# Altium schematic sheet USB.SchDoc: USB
size A4; Date: Not used; ApprovedBy: Not used; CheckedBy: Not used; Author: Not used; CompanyName: STMicroelectronics; DrawnBy: Not used; Engineer: Not used; Organization: Not used; Address1: Not used; Address2: Not used; Address3: Not used; Address4: Not used; DocumentNumber: 7; Revision: Not used; SheetNumber: 7; SheetTotal: 8
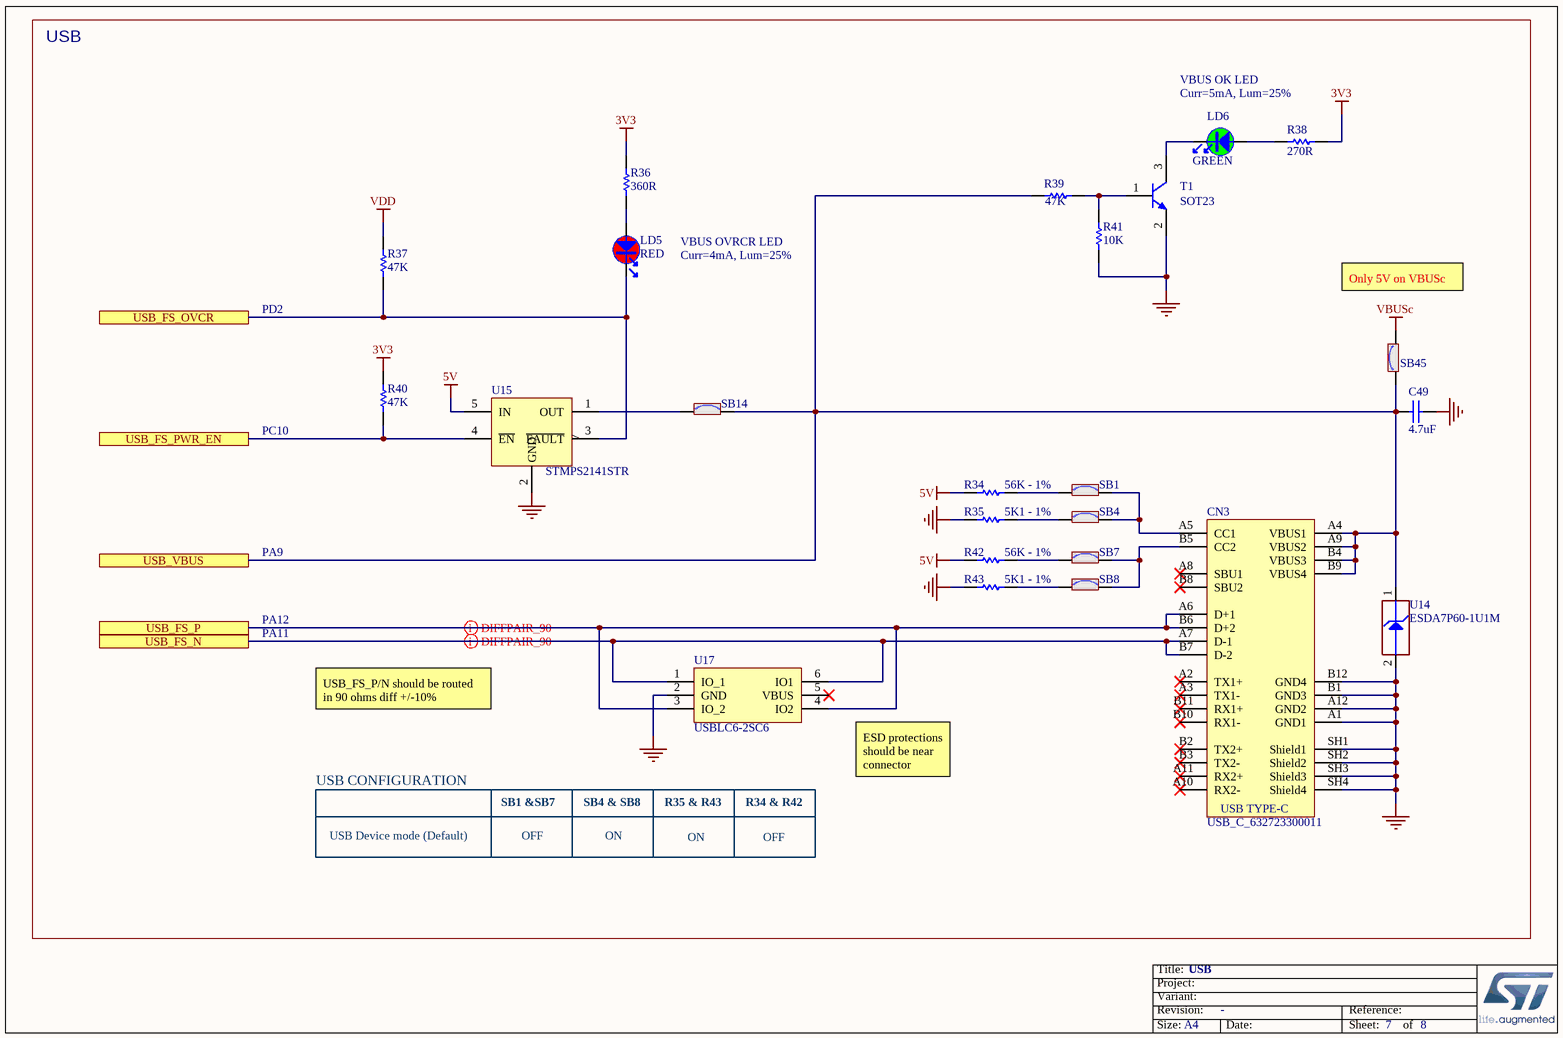
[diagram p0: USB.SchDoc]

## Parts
C49  value 4.7uF  [C0603]  (hidden comment: Capacitor)
CN3  value USB_C_632723300011  [CON_USB-TYPEC_WE_632723300011]  (hidden comment: USB_TYPE_C_Receptacle)
LD5  value RED  [LED_0603_VISHAY_VLMS1300-GS08_RED_1A2K_H0P8]  (hidden comment: LED_red)
LD6  value GREEN  [LED_0603_OSRAM_LG-Q396-PS-35_GREEN_1A2K_H0P4]  (hidden comment: LED_green)
R34  value 56K - 1%  [R0603]  (hidden comment: Resistor)
R35  value 5K1 - 1%  [R0603]  (hidden comment: Resistor)
R36  value 360R  [R0402]  (hidden comment: Resistor)
R37  value 47K  [R0402]  (hidden comment: Resistor)
R38  value 270R  [R0402]  (hidden comment: Resistor)
R39  value 47K  [R0402]  (hidden comment: Resistor)
R40  value 47K  [R0402]  (hidden comment: Resistor)
R41  value 10K  [R0402]  (hidden comment: Resistor)
R42  value 56K - 1%  [R0603]  (hidden comment: Resistor)
R43  value 5K1 - 1%  [R0603]  (hidden comment: Resistor)
SB1  (no value)  [SOLDER-BRIDGE_R0603-0R]
SB4  (no value)  [SOLDER-BRIDGE_R0603-0R]
SB7  (no value)  [SOLDER-BRIDGE_R0603-0R]
SB8  (no value)  [SOLDER-BRIDGE_R0603-0R]
SB14  (no value)  [SOLDER-BRIDGE_R0603-0R]
SB45  (no value)  [SOLDER-BRIDGE_R0603-0R]
T1  value SOT23  [NPN_SOT23]  (hidden comment: 9013-SOT23)
U14  value ESDA7P60-1U1M  [ESD_QFN2_1P6X1_P125]  (hidden comment: ESD-TRANSIL)
U15  STMPS2141STR  [MOS_SOT23-5L]
U17  USBLC6-2SC6  [ESD_SOT23-6L]

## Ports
USB_FS_N, USB_FS_OVCR, USB_FS_P, USB_FS_PWR_EN, USB_VBUS

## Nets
3V3: R36.2 R38.2 R40.1
5V: R34.1 R42.1 U15.5(IN)
GND: C49.1 CN3.A1(GND1) CN3.A12(GND2) CN3.B1(GND3) CN3.B12(GND4) CN3.SH1(Shield1) CN3.SH2(Shield2) CN3.SH3(Shield3) CN3.SH4(Shield4) R35.1 R41.1 R43.1 T1.2(E) U14.2(GND) U15.2(GND) U17.2(GND)
VBUSc: SB45.2
VDD: R37.1
USB_FS_N: CN3.A7(D-1) CN3.B7(D-2) U17.1(IO_1) U17.6(IO1) ; port USB_FS_N
USB_FS_OVCR: LD5.2 R37.2 U15.3(~{FAULT}) ; port USB_FS_OVCR
USB_FS_P: CN3.A6(D+1) CN3.B6(D+2) U17.3(IO_2) U17.4(IO2) ; port USB_FS_P
USB_FS_PWR_EN: R40.2 U15.4(~{EN}) ; port USB_FS_PWR_EN
USB_VBUS: C49.2 CN3.A4(VBUS1) CN3.A9(VBUS2) CN3.B4(VBUS3) CN3.B9(VBUS4) R39.1 SB14.2 SB45.1 U14.1(IO1) ; port USB_VBUS
NetCN3_A5: CN3.A5(CC1) SB1.2 SB4.2
NetCN3_B5: CN3.B5(CC2) SB7.2 SB8.2
NetLD5_1: LD5.1 R36.1
NetLD6_1: LD6.1 R38.1
NetLD6_2: LD6.2 T1.3(C)
NetR34_2: R34.2 SB1.1
NetR35_2: R35.2 SB4.1
NetR39_2: R39.2 R41.2 T1.1(B)
NetR42_2: R42.2 SB7.1
NetR43_2: R43.2 SB8.1
NetSB14_1: SB14.1 U15.1(OUT)

Not connected (* = marked no-connect by the designer): CN3 A2(TX1+)* A3(TX1-)* A8(SBU1)* A10(RX2-)* A11(RX2+)* B2(TX2+)* B3(TX2-)* B8(SBU2)* B10(RX1-)* B11(RX1+)*; U17 5(VBUS)*

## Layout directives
differential pair: USB_FS_N, USB_FS_P

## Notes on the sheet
- USB
- VBUS OK LED
- Curr=5mA, Lum=25%
- VBUS OVRCR LED
- PD2
- Curr=4mA, Lum=25%
- Only 5V on VBUSc
- PC10
- PA9
- PA11
- PA12
- USB_FS_P/N should be routed in 90 ohms diff +/-10%
- USB CONFIGURATION
- ESD protections should be near connector
- USB Device mode (Default)
- SB1 &SB7
- OFF
- SB4 & SB8
- ON
- R35 & R43
- R34 & R42

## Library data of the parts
C49 = MCD-00009: Capacitor, MLCC, 4.7uF, 16V, X5R, 10%, 0603, T=0.8mm; Manufacturer_Part_Number: CC0603KRX5R7BB475; Manufacturer: YAGEO; Provided_By: SUBCO; ECCN_US: EAR99; ECCN_EU: NEC
CN3 = MCD-02273: USB_TypeC, 24pins, RA, TH, T=1.9mm (USB certified); Part_Type: Connector; Part_Preference: Recommended; Manufacturer: WURTH ELEKTRONIK; Manufacturer_Part_Number: 632723300011; Component_Country_Of_Origin: China; ShowFields: YES; ID: 4373
LD5 = MCD-00587: LED Red, 0603 SMD, 2V Forward Voltage; Part_Type: Display; Manufacturer_Part_Number: VLMS1300-GS08; Manufacturer: VISHAY; Alternate_Manufacturer_Part_Number: LS Q976-NR-1; Alternate_Manufacturer: OSRAM OPTO SEMICONDUCTORS; Provided_By: SUBCO
LD6 = MCD-00588: LED Green, 0603 SMD, Forward Voltage Typ=2V, Max=2.5V; Part_Type: Display; Manufacturer_Part_Number: LG Q396-PS-35; Manufacturer: OSRAM OPTO SEMICONDUCTORS; Alternate_Manufacturer_Part_Number: VLMTG1300-GS08; Alternate_Manufacturer: VISHAY SEMICONDUCTOR OPTO DIVISION; Provided_By: SUBCO
R34 R42 = MCD-00494: Resistor, 56K, 0603, +/-1%, 1/10W; Part_Preference: Recommended; Manufacturer: YAGEO; Manufacturer_Part_Number: RC0603FR-0756KL
R35 R43 = MCD-00334: Resistor, 5K1, 0603, +/-1%, 1/10W; Part_Preference: Recommended; Manufacturer: YAGEO; Manufacturer_Part_Number: RC0603FR-075K1L
R36 = MCD-00461: Resistor,360R,0402,1%,1/16W; Manufacturer_Part_Number: RC0402FR-07360RL; Manufacturer: YAGEO; Provided_By: SUBCO; ECCN_US: EAR99; ECCN_EU: NEC
R37 R39 R40 = MCD-00063: Resistor,47K,0402,1%,1/16W; Manufacturer_Part_Number: RC0402FR-0747KL; Manufacturer: YAGEO; Provided_By: SUBCO; ECCN_US: EAR99; ECCN_EU: NEC
R38 = MCD-00441: Resistor,270R,0402,1%,1/16W; Manufacturer_Part_Number: RC0402FR-07270RL; Manufacturer: YAGEO; Provided_By: SUBCO; ECCN_US: EAR99; ECCN_EU: NEC
R41 = MCD-00053: Resistor,10K,0402,1%,1/16W; Manufacturer_Part_Number: RC0402FR-0710KL; Manufacturer: YAGEO; Provided_By: SUBCO; ECCN_US: EAR99; ECCN_EU: NEC
SB1 SB4 SB7 SB8 SB14 SB45 = MCD-00071: Solder Bridge ON; Part_Type: Mechanical; Manufacturer_Part_Number: RC0603JR-070RL; Manufacturer: YAGEO; Provided_By: SUBCO
T1 = MCD-00073: NPN Bipolar Transistor; Manufacturer_Part_Number: BSR14; Manufacturer: ON SEMICONDUCTOR; Part_Type: IC; Alternate_Manufacturer_Part_Number: MMBT2222ALT1G / MMBT2222ALT3G; Provided_By: SUBCO; ECCN_US: EAR99; ECCN_EU: NEC
U14 = MCD-00251: High power transient voltage suppressor, 7V breakdown; BMS_Part_Number: 9179042; Part_Type: Diode; Part_Preference: Recommended; Manufacturer: STMICROELECTRONICS; Manufacturer_HQ_COO: EU
U15 = MCD-00083: Enhanced single channel power switches with active low enable pin; Part_Type: IC; Manufacturer: STMICROELECTRONICS; Alternate_Manufacturer_Part_Number: TPS2041C; Alternate_Manufacturer: TEXAS INSTRUMENTS; BMS_Part_Number: 9159003; Provided_By: SUBCO with ST control; ECCN_US: EAR99; ECCN_EU: NEC
U17 = MCD-00163: Very low capacitance ESD protection; Part_Type: IC; Manufacturer: STMICROELECTRONICS; BMS_Part_Number: 9151075; Provided_By: SUBCO with ST control; ECCN_US: EAR99; ECCN_EU: NEC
